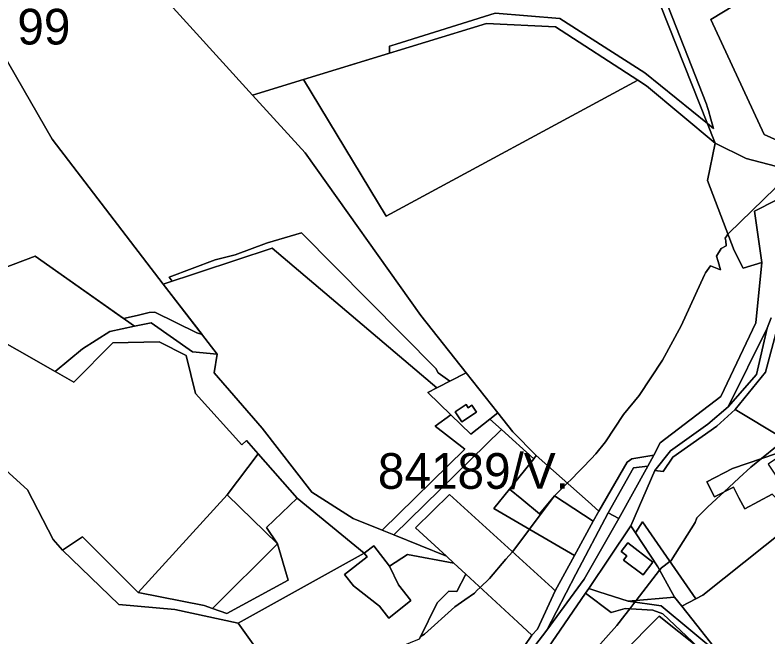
# Model space of a CAD drawing. Extents: x -477304 to -465429, y -1159113 to -1149210.
# Drawn here: x -472240.2 to -471923.8, y -1155652.4 to -1155391 of the extents above; entities that cross this region are included whole.
import ezdxf

# ---------------------------------------------------------------- set-up
doc = ezdxf.new("R2010")
doc.units = 0
for name, color, linetype in [('BPEJ_s', 7, 'Continuous'), ('ostatni_s', 7, 'Continuous'), ('PUPFL_s', 7, 'Continuous'), ('trav_porost_s', 7, 'Continuous'), ('voda_s', 7, 'Continuous'), ('zahrada_s', 7, 'Continuous')]:
    doc.layers.add(name, color=color, linetype=linetype)

msp = doc.modelspace()

# ---------------------------------------------------------------- linework, layer by layer
at = {"layer": 'BPEJ_s'}
for points in [[(-472295.85, -1155516.65), (-472231.81, -1155492.3), (-472194.58, -1155518.58), (-472188.88, -1155517.24), (-472183.8, -1155516.05), (-472181.46, -1155515.84), (-472163.82, -1155524.55), (-472161.64, -1155525.31), (-472177.93, -1155504.08), (-472174.23, -1155502.86), (-472175.43, -1155501.12), (-472156.17, -1155493.95), (-472147.67, -1155491.83), (-472134.5, -1155486.89), (-472134.08, -1155486.73), (-472119.84, -1155482.48), (-472063.32, -1155539.64), (-472062.47, -1155541.34), (-472057.43, -1155544.9), (-472050.58, -1155541.37), (-472069.72, -1155517.32), (-472118.36, -1155448.93), (-472140.39, -1155424.62), (-472119.05, -1155418.1), (-472082.8, -1155407.03), (-472082.87, -1155405.14), (-472082.91, -1155404.1), (-472081.93, -1155403.79), (-472080.11, -1155403.22), (-472038.46, -1155390.26), (-472011.26, -1155392.39), (-471975.57, -1155415.34), (-471949.27, -1155436.59), (-471946.72, -1155438.65), (-471947.76, -1155434.84), (-471948.8, -1155431.06), (-471949.19, -1155429.88), (-471949.64, -1155428.51), (-471968.66, -1155379.86)], [(-471968.66, -1155379.86), (-471949.64, -1155428.51), (-471949.19, -1155429.88), (-471948.8, -1155431.06), (-471947.76, -1155434.84), (-471946.72, -1155438.65), (-471949.27, -1155436.59), (-471975.57, -1155415.34), (-472011.26, -1155392.39), (-472038.46, -1155390.26), (-472080.11, -1155403.22), (-472081.93, -1155403.79), (-472082.91, -1155404.1), (-472082.87, -1155405.14), (-472082.8, -1155407.03), (-472119.05, -1155418.1), (-472140.39, -1155424.62), (-472118.36, -1155448.93), (-472069.72, -1155517.32), (-472050.58, -1155541.37), (-472057.43, -1155544.9), (-472062.47, -1155541.34), (-472063.32, -1155539.64), (-472119.84, -1155482.48), (-472134.08, -1155486.73), (-472134.5, -1155486.89), (-472147.67, -1155491.83), (-472156.17, -1155493.95), (-472175.43, -1155501.12), (-472174.23, -1155502.86), (-472177.93, -1155504.08), (-472161.64, -1155525.31), (-472163.82, -1155524.55), (-472181.46, -1155515.84), (-472183.8, -1155516.05)], [(-471833.6, -1155385.91), (-471839.13, -1155392.89), (-471852.21, -1155409.42), (-471854.03, -1155411.72), (-471865.5, -1155423.83), (-471872.73, -1155430.42), (-471874.43, -1155431.06), (-471878.25, -1155434.88), (-471890.15, -1155444.23), (-471900.08, -1155450.89), (-471901.66, -1155451.94), (-471908.85, -1155456.77), (-471909.9, -1155457.39), (-471920.75, -1155463.78), (-471940.3, -1155482.69), (-471940.62, -1155483.15), (-471941.08, -1155483.81), (-471941.78, -1155484.82)], [(-472033.9, -1155619.72), (-472031.21, -1155616.57), (-472029.75, -1155614.85), (-472024.02, -1155607.16), (-472013.6, -1155593.18), (-472013.5, -1155593.08), (-472008.14, -1155587.76), (-472006.39, -1155586.03), (-472003.23, -1155582.89), (-472001.69, -1155581.28), (-471998.07, -1155577.49), (-471996.1, -1155575.44), (-471992.14, -1155570.45), (-471984.49, -1155558.97), (-471977.91, -1155550.9), (-471968.13, -1155536.02), (-471960.27, -1155521.57), (-471950.51, -1155500.21), (-471950.1, -1155499.31), (-471947.9, -1155496.42), (-471943.72, -1155498.14), (-471944.8, -1155494.63), (-471945.49, -1155492.41), (-471943.52, -1155489.13), (-471941.39, -1155488.02), (-471941.57, -1155485.88), (-471941.78, -1155484.82), (-471941.08, -1155483.81), (-471940.62, -1155483.15), (-471940.3, -1155482.69), (-471920.75, -1155463.78)], [(-472183.8, -1155516.05), (-472188.88, -1155517.24), (-472194.58, -1155518.58), (-472231.81, -1155492.3), (-472295.85, -1155516.65), (-472331.25, -1155485.33), (-472341.5, -1155490.42), (-472339.07, -1155506.11), (-472339.08, -1155506.49), (-472366.04, -1155537.09), (-472363.13, -1155538.36), (-472340.18, -1155548.35), (-472332.53, -1155552.17), (-472331.68, -1155553.45), (-472331.68, -1155593.82), (-472333.17, -1155596.79), (-472334.47, -1155598.37), (-472345.46, -1155611.64), (-472375.3, -1155647.69), (-472373.94, -1155647.96), (-472371.63, -1155648.42), (-472318.84, -1155656.72)], [(-471941.78, -1155484.82), (-471941.57, -1155485.88), (-471941.39, -1155488.02), (-471943.52, -1155489.13), (-471945.49, -1155492.41), (-471944.8, -1155494.63), (-471943.72, -1155498.14), (-471947.9, -1155496.42), (-471950.1, -1155499.31), (-471950.51, -1155500.21), (-471960.27, -1155521.57), (-471968.13, -1155536.02), (-471977.91, -1155550.9), (-471984.49, -1155558.97), (-471992.14, -1155570.45), (-471996.1, -1155575.44), (-471998.07, -1155577.49), (-472001.69, -1155581.28), (-472003.23, -1155582.89), (-472006.39, -1155586.03), (-472008.14, -1155587.76), (-472013.5, -1155593.08), (-472013.6, -1155593.18), (-472024.02, -1155607.16), (-472029.75, -1155614.85), (-472031.21, -1155616.57), (-472033.9, -1155619.72), (-472040.8, -1155627.81), (-472044.73, -1155631.61), (-472045.95, -1155632.79), (-472047.17, -1155633.98), (-472051.17, -1155636.75), (-472055.46, -1155639.71), (-472068.21, -1155651.19), (-472069.91, -1155652.42)], [(-472004.72, -1155667.12), (-471987.3, -1155647.63), (-471983.95, -1155643.31), (-471981.87, -1155640.61), (-471979.71, -1155637.82), (-471979.19, -1155637.14), (-471969.33, -1155624.38), (-471968.56, -1155623.37), (-471965.01, -1155620.71), (-471964.45, -1155620.29), (-471954.42, -1155604.28), (-471953.68, -1155602.32), (-471951.65, -1155600.29), (-471949.22, -1155597.85), (-471945.43, -1155594.38), (-471942.34, -1155591.54), (-471935.87, -1155585.59), (-471930.95, -1155581.07), (-471926.47, -1155577.45), (-471919.9, -1155572.14)], [(-471919.9, -1155572.14), (-471926.47, -1155577.45), (-471930.95, -1155581.07), (-471935.87, -1155585.59), (-471942.34, -1155591.54), (-471945.43, -1155594.38), (-471949.22, -1155597.85), (-471951.65, -1155600.29), (-471953.68, -1155602.32), (-471954.42, -1155604.28), (-471964.45, -1155620.29), (-471965.01, -1155620.71), (-471968.56, -1155623.37), (-471969.33, -1155624.38), (-471979.19, -1155637.14)], [(-472069.91, -1155652.42), (-472068.21, -1155651.19), (-472055.46, -1155639.71), (-472051.17, -1155636.75), (-472047.17, -1155633.98), (-472045.95, -1155632.79), (-472044.73, -1155631.61), (-472040.8, -1155627.81), (-472033.9, -1155619.72)], [(-471979.19, -1155637.14), (-471979.71, -1155637.82), (-471981.87, -1155640.61), (-471983.95, -1155643.31), (-471987.3, -1155647.63), (-472004.72, -1155667.12)]]:
    msp.add_lwpolyline(points, dxfattribs=at)
at = {"layer": 'ostatni_s'}
for points in [[(-471919.93, -1155522.83), (-471924.8, -1155541.1), (-471937.53, -1155556.87), (-471945.29, -1155563.87), (-471963.8, -1155576.84), (-471967.88, -1155582.83), (-471971.35, -1155582.39), (-471964.78, -1155574.2), (-471949.02, -1155562.96), (-471940.6, -1155555.69), (-471928.57, -1155542.07), (-471924.12, -1155522.69), (-471922.43, -1155518.27)], [(-472031.37, -1155663.79), (-472022.99, -1155651.66), (-472020.68, -1155649.16), (-472013.19, -1155632.97), (-472005.07, -1155618.13), (-471997.23, -1155603.81), (-471994.89, -1155599.53), (-471982.92, -1155579), (-471981.08, -1155577.52), (-471971.77, -1155576.03), (-471974.33, -1155580.64), (-471980.37, -1155581.3), (-471990.92, -1155600.3), (-472004.52, -1155626.01), (-472016.74, -1155649.59), (-472021.75, -1155656.1)]]:
    msp.add_lwpolyline(points, dxfattribs=at)
for points in [[(-471940.6, -1155555.69), (-471924.12, -1155522.69), (-471928.57, -1155542.07)], [(-472055.26, -1155557.75), (-472050.65, -1155554.7), (-472049.76, -1155556.04), (-472048.25, -1155555.04), (-472046.36, -1155557.9), (-472052.49, -1155561.95)], [(-471994.89, -1155599.53), (-471997.23, -1155603.81), (-472013.52, -1155593.06), (-472019.8, -1155600.71), (-472027.3, -1155594.56), (-472032.48, -1155590.31), (-472022.26, -1155577.58), (-472021.15, -1155576.2), (-471999.43, -1155595.49)], [(-471938.35, -1155589.45), (-471946.21, -1155593.56), (-471949.51, -1155587.19), (-471938.66, -1155581.57), (-471913.99, -1155573.24), (-471923.69, -1155579.74), (-471920.43, -1155584.83), (-471910.49, -1155578.46), (-471915.16, -1155592.84), (-471918.67, -1155595.8), (-471922.04, -1155592.46), (-471933.5, -1155598.57), (-471935.99, -1155593.89)], [(-471990.92, -1155600.3), (-471980.37, -1155581.3), (-471974.33, -1155580.64), (-471986.51, -1155602.63)], [(-472016.74, -1155649.59), (-472004.52, -1155626.01), (-471990.92, -1155600.3), (-471986.51, -1155602.63), (-472000.98, -1155628.09)], [(-471994.85, -1155633.42), (-471999.11, -1155632.04), (-471981.43, -1155605.69), (-471979.5, -1155608.64), (-471970.12, -1155622.96), (-471963.05, -1155635.71), (-471982.5, -1155637.43)], [(-472098.02, -1155630.86), (-472101.71, -1155626.14), (-472092.26, -1155618.75), (-472093.43, -1155617.25), (-472089.49, -1155614.17), (-472082.91, -1155622.59), (-472079.13, -1155630.44), (-472073.86, -1155637.09), (-472083.19, -1155644.49), (-472087.11, -1155639.54)], [(-471982.66, -1155612.81), (-471972.21, -1155620.98), (-471976.31, -1155626.29), (-471984.52, -1155620.19), (-471983.1, -1155618.36), (-471985.52, -1155616.47)], [(-471983.1, -1155618.36), (-471984.52, -1155620.19), (-471976.31, -1155626.29), (-471972.21, -1155620.98), (-471982.66, -1155612.81), (-471985.52, -1155616.47)], [(-471943.72, -1155660.03), (-471924.24, -1155689.99), (-471921.07, -1155699.04), (-471924.18, -1155700.87), (-471927.8, -1155691.67), (-471932.16, -1155687.43), (-471941.21, -1155674.75), (-471944.74, -1155669), (-471947.72, -1155662.57), (-471952.94, -1155656.89), (-471967.93, -1155642.72), (-471972.26, -1155641.2), (-471983.88, -1155640.49), (-471989.76, -1155642.15), (-472000.47, -1155634.07), (-471999.11, -1155632.04), (-471994.85, -1155633.42), (-471982.5, -1155637.43), (-471968.73, -1155639.36)], [(-471968.73, -1155639.36), (-471982.5, -1155637.43), (-471963.05, -1155635.71), (-471960.02, -1155639.53), (-471943.72, -1155660.03)]]:
    msp.add_lwpolyline(points, close=True, dxfattribs=at)
at = {"layer": 'PUPFL_s'}
for points in [[(-471978.52, -1155418.44), (-472013.08, -1155396.02), (-472042.04, -1155394.59), (-472119.05, -1155418.1), (-472140.39, -1155424.62), (-472219.36, -1155337.48), (-472243.84, -1155329.66), (-472248.44, -1155321.6), (-472242.09, -1155309.1), (-472238.49, -1155308.73), (-472234.23, -1155308.29), (-472226.18, -1155307.46), (-472206.39, -1155305.48), (-472203.48, -1155305.23), (-472189.74, -1155304.42), (-472170.84, -1155303.3), (-472166.4, -1155302.97), (-472117.01, -1155299.35), (-472076.73, -1155296.25), (-472068.38, -1155295.6), (-472046.8, -1155293.92), (-472004.87, -1155296.39), (-471946.02, -1155444.8), (-471974.85, -1155420.81)], [(-471925.54, -1155341.33), (-471903.53, -1155365.92), (-471910.13, -1155369.93), (-471947.81, -1155392.86), (-471925.41, -1155441.19), (-471898.09, -1155453.56), (-471895.02, -1155457.66), (-471901.94, -1155459.49), (-471932.96, -1155451.3), (-471946.02, -1155444.8), (-472004.87, -1155296.39), (-471991.84, -1155296.54), (-471972, -1155296.45), (-471926.2, -1155295.14), (-471904.65, -1155294.79), (-471876.71, -1155295.3), (-471859.51, -1155320.16), (-471900.43, -1155305.78), (-471929.53, -1155317.48), (-471935.15, -1155319.74)], [(-472243.84, -1155329.66), (-472219.36, -1155337.48), (-472140.39, -1155424.62), (-472118.36, -1155448.93), (-472069.72, -1155517.32), (-472050.58, -1155541.37), (-472062.99, -1155547.77), (-472132.09, -1155488.99), (-472177.93, -1155504.08), (-472224.55, -1155443.11), (-472273.5, -1155358.25)], [(-471934.24, -1155497.43), (-471938.06, -1155489.92), (-471949.18, -1155460.49), (-471946.02, -1155444.8), (-471932.96, -1155451.3), (-471901.94, -1155459.49), (-471929.41, -1155473.44), (-471926.37, -1155495.04)]]:
    msp.add_lwpolyline(points, close=True, dxfattribs=at)
msp.add_lwpolyline([(-472489.39, -1155525.15), (-472414.35, -1155521.25), (-472432.84, -1155512.62), (-472404.16, -1155484.17), (-472273.5, -1155358.25), (-472224.55, -1155443.11), (-472177.93, -1155504.08), (-472155.34, -1155533.52), (-472165.7, -1155532.61), (-472182.96, -1155520.34), (-472190.01, -1155521.81), (-472231.81, -1155492.3), (-472295.85, -1155516.65), (-472331.25, -1155485.33), (-472341.5, -1155490.42), (-472339.07, -1155506.11), (-472369.77, -1155540.29), (-472335.24, -1155555.26), (-472334.46, -1155599.17), (-472379.12, -1155649.8), (-472315.8, -1155660.22)], dxfattribs=at)
at = {"layer": 'trav_porost_s'}
for points in [[(-471863.45, -1155410.1), (-471906.37, -1155442.49), (-471898.09, -1155453.56), (-471925.41, -1155441.19), (-471947.81, -1155392.86), (-471910.13, -1155369.93), (-471882.73, -1155399.76), (-471877.99, -1155395.6)], [(-471978.52, -1155418.44), (-472084.21, -1155475.55), (-472119.05, -1155418.1), (-472042.04, -1155394.59), (-472013.08, -1155396.02)], [(-472069.72, -1155517.32), (-472118.36, -1155448.93), (-472140.39, -1155424.62), (-472119.05, -1155418.1), (-472084.21, -1155475.55), (-471978.52, -1155418.44), (-471974.85, -1155420.81), (-471946.02, -1155444.8), (-471949.18, -1155460.49), (-471938.06, -1155489.92), (-471934.24, -1155497.43), (-471926.37, -1155495.04), (-471928.9, -1155520.44), (-471943.64, -1155551.32), (-471969.11, -1155570.76), (-471971.77, -1155576.03), (-471981.08, -1155577.52), (-471982.92, -1155579), (-471994.89, -1155599.53), (-471999.43, -1155595.49), (-472021.15, -1155576.2), (-472031.03, -1155566.18), (-472037.31, -1155558.21), (-472050.58, -1155541.37)], [(-472231.81, -1155492.3), (-472190.01, -1155521.81), (-472200.44, -1155523.98), (-472211.83, -1155531.3), (-472223.38, -1155540.87), (-472271.42, -1155513.45), (-472302.43, -1155529.25), (-472265.52, -1155563.04), (-472270.38, -1155566.03), (-472309.67, -1155531.03), (-472339.07, -1155506.11), (-472341.5, -1155490.42), (-472331.25, -1155485.33), (-472295.85, -1155516.65)], [(-472098.06, -1155602.61), (-472115.42, -1155591.6), (-472136.4, -1155564.66), (-472156.53, -1155541.43), (-472155.34, -1155533.52), (-472177.93, -1155504.08), (-472132.09, -1155488.99), (-472062.99, -1155547.77), (-472066.7, -1155549.68), (-472057.01, -1155559.02), (-472063.66, -1155563.86), (-472051.18, -1155573.49), (-472085.95, -1155607.53)], [(-472179.67, -1155528.39), (-472168.35, -1155534.06), (-472164.32, -1155550.11), (-472144.95, -1155571.64), (-472142.94, -1155569.88), (-472138.02, -1155575.46), (-472151.08, -1155592.69), (-472188.43, -1155633.67), (-472211.86, -1155610.38), (-472220.23, -1155615.89), (-472224.24, -1155611.43), (-472234.98, -1155590.51), (-472265.52, -1155563.04), (-472302.43, -1155529.25), (-472271.42, -1155513.45), (-472223.38, -1155540.87), (-472215.53, -1155545.35), (-472199.12, -1155528.78)], [(-472121.61, -1155594.1), (-472138.02, -1155575.46), (-472142.94, -1155569.88), (-472144.95, -1155571.64), (-472164.32, -1155550.11), (-472168.35, -1155534.06), (-472179.67, -1155528.39), (-472199.12, -1155528.78), (-472215.53, -1155545.35), (-472223.38, -1155540.87), (-472211.83, -1155531.3), (-472200.44, -1155523.98), (-472190.01, -1155521.81), (-472182.96, -1155520.34), (-472165.7, -1155532.61), (-472155.34, -1155533.52), (-472156.53, -1155541.43), (-472136.4, -1155564.66), (-472115.42, -1155591.6), (-472098.06, -1155602.61), (-472085.95, -1155607.53), (-472081.02, -1155609.54), (-472058.92, -1155618.52), (-472055.84, -1155621.36), (-472075.24, -1155617.75), (-472082.91, -1155622.59), (-472089.49, -1155614.17), (-472093.43, -1155617.25)], [(-471919.93, -1155522.83), (-471888.2, -1155552.55), (-471869.3, -1155570.26), (-471874.19, -1155572.79), (-471880.05, -1155565.8), (-471885.18, -1155564.45), (-471899.98, -1155565.27), (-471914.15, -1155570.68), (-471918.23, -1155568.5), (-471937.53, -1155556.87), (-471924.8, -1155541.1)], [(-472062.99, -1155547.77), (-472050.58, -1155541.37), (-472037.31, -1155558.21), (-472040.65, -1155560.84), (-472048.62, -1155567.11), (-472057.01, -1155559.02), (-472066.7, -1155549.68)], [(-472048.25, -1155555.04), (-472049.76, -1155556.04), (-472050.65, -1155554.7), (-472055.26, -1155557.75), (-472052.49, -1155561.95), (-472046.36, -1155557.9)], [(-472081.02, -1155609.54), (-472085.95, -1155607.53), (-472051.18, -1155573.49), (-472063.66, -1155563.86), (-472057.01, -1155559.02), (-472048.62, -1155567.11), (-472040.65, -1155560.84), (-472035.82, -1155565.24)], [(-472031.03, -1155566.18), (-472021.15, -1155576.2), (-472022.26, -1155577.58), (-472035.82, -1155565.24), (-472040.65, -1155560.84), (-472037.31, -1155558.21)], [(-472058.92, -1155618.52), (-472081.02, -1155609.54), (-472035.82, -1155565.24), (-472022.26, -1155577.58), (-472032.48, -1155590.31), (-472039.04, -1155598.48), (-472023.89, -1155607.24), (-472005.07, -1155618.13), (-472013.19, -1155632.97), (-472014.52, -1155631.76), (-472057.68, -1155592.5), (-472071.97, -1155606.49)], [(-472151.08, -1155592.69), (-472138.02, -1155575.46), (-472121.61, -1155594.1), (-472134.51, -1155606.36), (-472129.98, -1155613.25)], [(-472173.08, -1155640.92), (-472196.64, -1155638.72), (-472220.23, -1155615.89), (-472211.86, -1155610.38), (-472188.43, -1155633.67), (-472160.77, -1155639.13), (-472157.17, -1155640.42), (-472151.15, -1155642.59), (-472125.43, -1155628.53), (-472129.98, -1155613.25), (-472134.51, -1155606.36), (-472121.61, -1155594.1), (-472093.43, -1155617.25), (-472146.39, -1155646.68)], [(-472160.77, -1155639.13), (-472188.43, -1155633.67), (-472151.08, -1155592.69), (-472129.98, -1155613.25), (-472157.17, -1155640.42)], [(-472020.68, -1155649.16), (-472022.99, -1155651.66), (-472028.87, -1155646.24), (-472050.81, -1155626), (-472055.84, -1155621.36), (-472058.92, -1155618.52), (-472071.97, -1155606.49), (-472057.68, -1155592.5), (-472014.52, -1155631.76), (-472013.19, -1155632.97)], [(-471859.76, -1155700.11), (-471870.33, -1155705.64), (-471878.8, -1155713.38), (-471860.1, -1155746.65), (-471895.47, -1155764.33), (-471902.27, -1155752.41), (-471921.07, -1155699.04), (-471924.24, -1155689.99), (-471943.72, -1155660.03), (-471960.02, -1155639.53), (-471954.16, -1155636.38), (-471951.2, -1155634.78), (-471907.71, -1155600.3), (-471882.13, -1155630.97), (-471869.24, -1155640.55), (-471861.67, -1155670.03), (-471858.42, -1155683.15)], [(-471954.16, -1155636.38), (-471960.02, -1155639.53), (-471963.05, -1155635.71), (-471970.12, -1155622.96), (-471979.5, -1155608.64), (-471976.6, -1155603.99)], [(-472129.98, -1155613.25), (-472125.43, -1155628.53), (-472151.15, -1155642.59), (-472157.17, -1155640.42)], [(-472062.76, -1155638.04), (-472057.91, -1155633.21), (-472054.52, -1155633.37), (-472050.81, -1155626), (-472028.87, -1155646.24), (-472022.99, -1155651.66), (-472031.37, -1155663.79), (-472048.03, -1155677.17), (-472058.91, -1155668.07), (-472077.81, -1155656.26), (-472070.3, -1155653.2)], [(-471985.18, -1155659.55), (-471986.08, -1155660.46), (-471990.8, -1155670.54), (-471997.22, -1155676.06), (-472004.39, -1155666.86), (-472015.74, -1155675.94), (-472021.59, -1155670.5), (-472016.38, -1155657.19), (-472000.47, -1155634.07), (-471989.76, -1155642.15), (-471983.88, -1155640.49), (-471972.26, -1155641.2), (-471967.93, -1155642.72), (-471952.94, -1155656.89), (-471969.52, -1155643.65)], [(-471960.91, -1155663.38), (-471957.74, -1155669.62), (-471966.99, -1155675.78), (-471985.18, -1155659.55), (-471969.52, -1155643.65), (-471952.94, -1155656.89)]]:
    msp.add_lwpolyline(points, close=True, dxfattribs=at)
for points in [[(-472295.39, -1155663.02), (-472292.17, -1155642.84), (-472296.83, -1155599.4), (-472313.52, -1155584.44), (-472324.27, -1155596.83), (-472325.54, -1155560.17), (-472339.57, -1155527.53), (-472339.07, -1155506.11), (-472309.67, -1155531.03), (-472270.38, -1155566.03), (-472265.52, -1155563.04), (-472234.98, -1155590.51), (-472224.24, -1155611.43), (-472220.23, -1155615.89), (-472196.64, -1155638.72), (-472173.08, -1155640.92), (-472146.39, -1155646.68), (-472137.32, -1155659.34)], [(-471907.71, -1155600.3), (-471951.2, -1155634.78), (-471954.16, -1155636.38), (-471976.6, -1155603.99), (-471979.5, -1155608.64), (-471981.43, -1155605.69), (-471971.35, -1155582.39), (-471967.88, -1155582.83), (-471963.8, -1155576.84), (-471945.29, -1155563.87), (-471937.53, -1155556.87), (-471918.23, -1155568.5)], [(-471913.99, -1155573.24), (-471938.66, -1155581.57), (-471949.51, -1155587.19), (-471946.21, -1155593.56), (-471938.35, -1155589.45), (-471935.99, -1155593.89), (-471933.5, -1155598.57), (-471922.04, -1155592.46)], [(-472137.32, -1155659.34), (-472146.39, -1155646.68), (-472093.43, -1155617.25), (-472092.26, -1155618.75), (-472101.71, -1155626.14), (-472098.02, -1155630.86), (-472087.11, -1155639.54), (-472083.19, -1155644.49), (-472073.86, -1155637.09), (-472079.13, -1155630.44), (-472082.91, -1155622.59), (-472075.24, -1155617.75), (-472055.84, -1155621.36), (-472050.81, -1155626), (-472054.52, -1155633.37), (-472057.91, -1155633.21), (-472062.76, -1155638.04), (-472070.3, -1155653.2)]]:
    msp.add_lwpolyline(points, dxfattribs=at)
at = {"layer": 'voda_s'}
for points in [[(-472021.75, -1155656.1), (-472016.74, -1155649.59), (-472000.98, -1155628.09), (-471986.51, -1155602.63), (-471974.33, -1155580.64), (-471971.77, -1155576.03), (-471969.11, -1155570.76), (-471943.64, -1155551.32), (-471928.9, -1155520.44), (-471926.37, -1155495.04), (-471929.41, -1155473.44), (-471901.94, -1155459.49)], [(-471922.43, -1155518.27), (-471924.12, -1155522.69), (-471940.6, -1155555.69), (-471949.02, -1155562.96), (-471964.78, -1155574.2), (-471971.35, -1155582.39), (-471981.43, -1155605.69), (-471999.11, -1155632.04), (-472000.47, -1155634.07), (-472016.38, -1155657.19)]]:
    msp.add_lwpolyline(points, dxfattribs=at)
at = {"layer": 'zahrada_s'}
msp.add_lwpolyline([(-472027.3, -1155594.56), (-472019.8, -1155600.71), (-472013.52, -1155593.06), (-471997.23, -1155603.81), (-472005.07, -1155618.13), (-472023.89, -1155607.24), (-472039.04, -1155598.48), (-472032.48, -1155590.31)], close=True, dxfattribs=at)

# ---------------------------------------------------------------- texts
at = {"layer": 'BPEJ_s'}
for s, p in [('99', (-472239.26, -1155403.39)), ('84189/V.', (-472087.74, -1155590.15))]:
    msp.add_text(s, height=15, dxfattribs=at).set_placement(p)

doc.saveas('drawing.dxf')
